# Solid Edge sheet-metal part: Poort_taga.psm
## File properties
Author: Olev
Template: Normal.psm
Last saved by: Olev
Revision: 9
Application: Solid Edge
Accuracy: 0,990
Material Thickness: 0,50 mm
Bend Radius: 1,00 mm
Relief Width: 1,00 mm
Relief Length: 0,00 mm
Neutral Factor: 0,330
Minimum Arc Length: 0,10 mm
Deviational Tolerance: 0,10 mm
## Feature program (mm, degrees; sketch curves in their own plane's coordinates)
base tab "unnamed BaseTab 1"
flange "Flange_3"
flange "Flange_4"
dimple "Dimple_2"
dimple "Dimple_3"
dimple "Dimple_4"
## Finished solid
Body 1: solid body, 44 faces, 108 edges, 72 vertices.
  Faces by surface: cylinder 28, plane 16
  Edges by curve: line 76, ellipse 24, circle 8
Bounding box of the edges (mm): 8.000 x 64.000 x 4.000, from (-8, -32, 0) to (0, 32, 4).
Cylindrical faces by radius (mm): R0.5 x24, R1 x2, R1.5 x2
Planar faces by outward normal: +x 2, +y 4, +z 1, -x 4, -y 4, -z 1
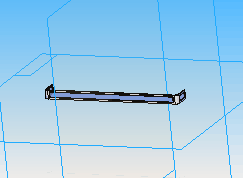
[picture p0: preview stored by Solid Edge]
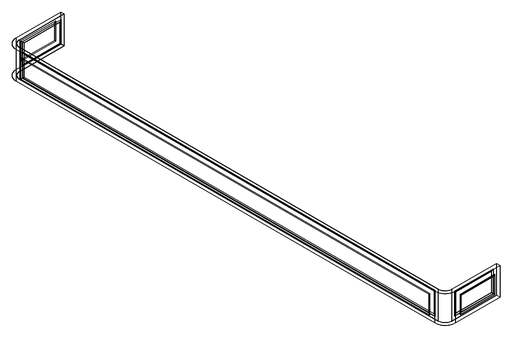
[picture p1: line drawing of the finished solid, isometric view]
